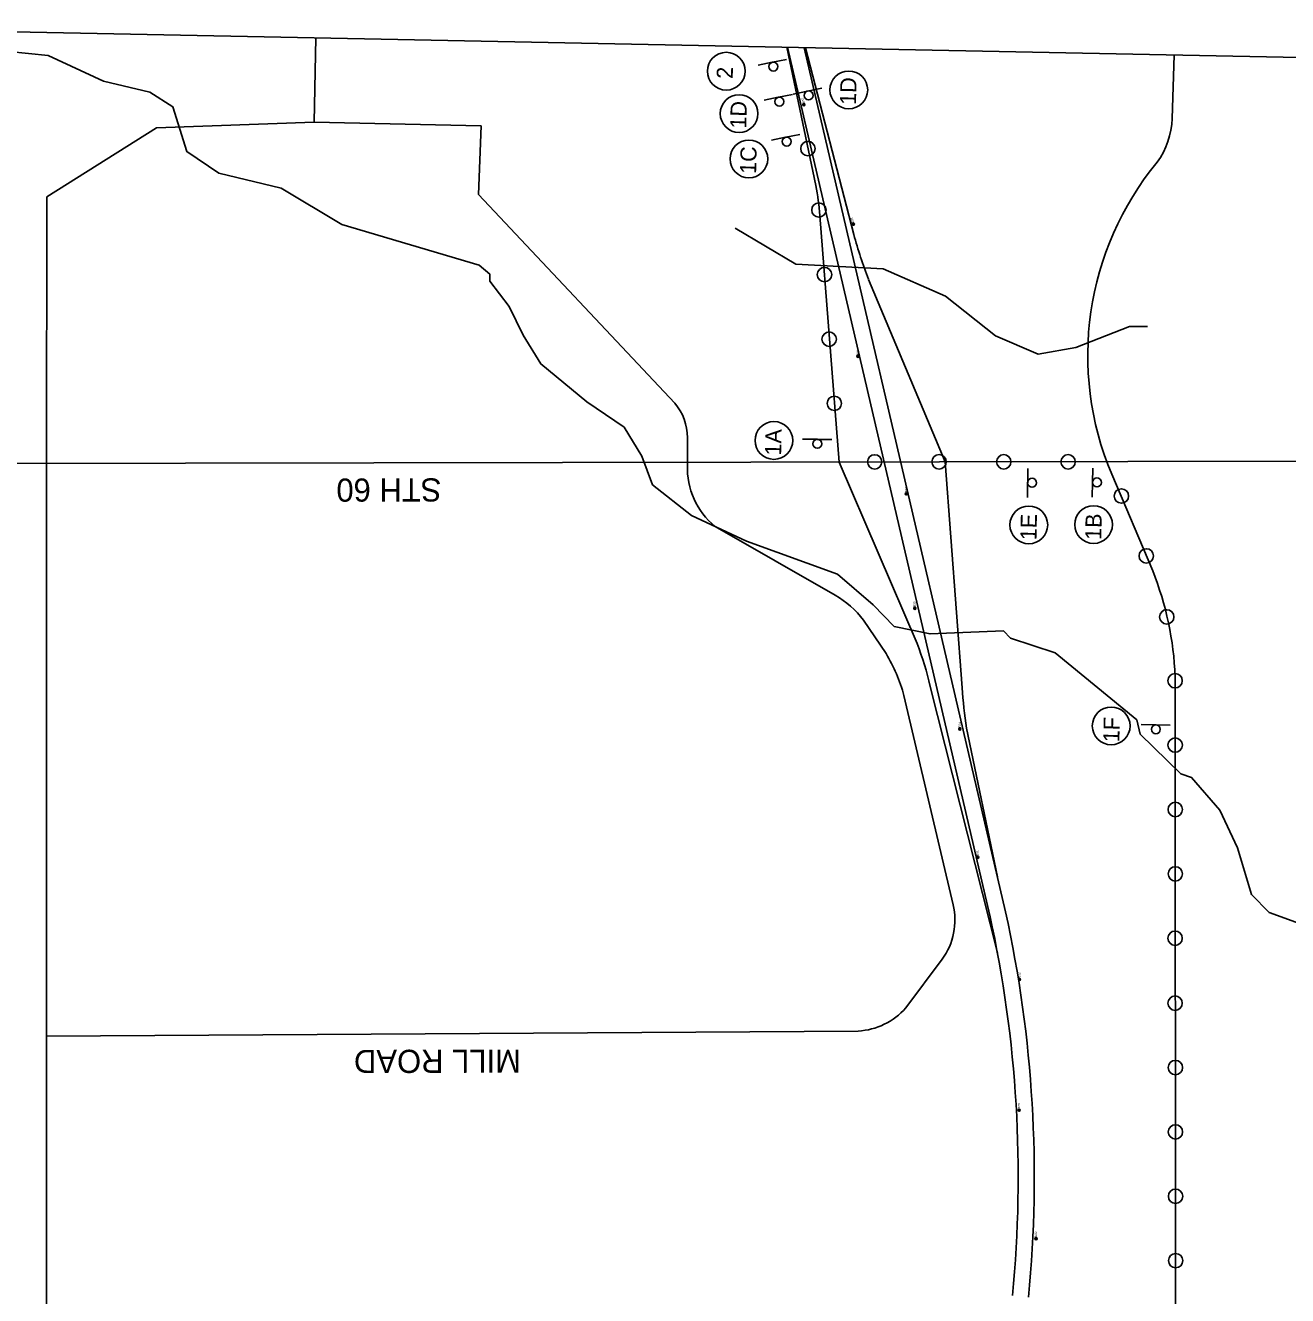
# Model space of a CAD drawing. Extents: x 331323 to 388339, y 121519 to 205315.
# Drawn here: x 357309 to 363194, y 144251 to 150171 of the extents above; entities that cross this region are included whole.
import ezdxf

# ---------------------------------------------------------------- set-up
doc = ezdxf.new("R2010")
doc.units = 0
for name, color, linetype in [('CA-TEXT', 7, 'Continuous'), ('CE-TOPO-CONC-SLAB', 7, 'Continuous'), ('E_SOIL_BORE1 [KAPUR_CADDS_LEVELS]', 7, 'Continuous'), ('E_SOIL_BORE2 [KAPUR_CADDS_LEVELS]', 7, 'Continuous'), ('Level 2', 7, 'Continuous'), ('Level 3', 7, 'Continuous'), ('Level 4', 7, 'Continuous'), ('Level 57', 7, 'Continuous'), ('P_MARK', 7, 'Continuous'), ('PLT_Sheet_Info', 7, 'Continuous'), ('SIGNS-POLES', 7, 'Continuous')]:
    doc.layers.add(name, color=color, linetype=linetype)

msp = doc.modelspace()

# ---------------------------------------------------------------- linework, layer by layer
at = {"layer": 'CA-TEXT'}
for centre in [(360576.8, 149957.2), (361147.9, 149870.1), (360636.3, 149759.4), (360682.2, 149548.3), (360798.8, 148236.2), (361987.2, 147842.8), (362289.2, 147844.4), (362371.3, 146906.1)]:
    msp.add_circle(centre, 88, dxfattribs=at)
at = {"layer": 'CE-TOPO-CONC-SLAB'}
for centre in [(360957.2, 149596.5), (361008.3, 149310.2), (361034.7, 149009.2), (361056.4, 148708.3), (361080.6, 148409.2), (361268.6, 148136.6), (361568.7, 148136.7), (361870.4, 148136.7), (362170.4, 148136.8), (362418.9, 147977.5), (362534.8, 147698.5), (362630.5, 147414.2), (362669.3, 147116.6), (362669.6, 146816.6), (362670, 146516.6), (362670.3, 146216.6), (362669.3, 145916.6), (362669.3, 145614.1), (362670.7, 145314), (362671, 145014.1), (362671.3, 144714.1), (362671.7, 144414.1)]:
    msp.add_circle(centre, 33.5, dxfattribs=at)
at = {"layer": 'Level 2'}
for p, q in [((360993.9, 149424.2), (360859.4, 150068.4)), ((361805.5, 146023.2), (360862.5, 150068.4)), ((361878.5, 146040.2), (360939.9, 150066.8)), ((361171, 149195.5), (360945.9, 150066.7)), ((361102.9, 148135.5), (361012.8, 149285)), ((361597.4, 148136.4), (361239.3, 148987.2)), ((361102.9, 148135.5), (361466.5, 147289.5)), ((361597.4, 148136.4), (361676.1, 147084)), ((361528, 147090.3), (361841.1, 145848)), ((361696.2, 146895.8), (361840.7, 146202.3))]:
    msp.add_line(p, q, dxfattribs=at)
for centre, radius, start, end in [((359828.4, 149195), 1187.8, 4.34586, 11.12726), ((363539.2, 149856.5), 2458.6, 195.59569, 200.70516), ((359972.6, 146718.9), 1599.2, 13.4307, 20.90561), ((364297.5, 147267.9), 2627.8, 184.01299, 188.13954), ((356248.8, 144803.5), 5764, 354.42954, 12.3898), ((356248.8, 144803.5), 5689, 354.42954, 12.3898)]:
    msp.add_arc(centre, radius, start, end, dxfattribs=at)
at = {"layer": 'Level 3'}
for p, q in [((362655.2, 149736.6), (362664.2, 150032.1)), ((363933.7, 148140.4), (355745.4, 148126.3)), ((362374.1, 148078.8), (362564.7, 147628.5)), ((362672.8, 142845.1), (362669.2, 147136.3))]:
    msp.add_line(p, q, dxfattribs=at)
for centre, radius, start, end in [((362295.7, 149745.7), 359.6, 323.74261, 358.54958), ((363679.7, 148631.4), 1417.7, 140.50233, 202.93922), ((361200.1, 147081.5), 1470.2, 2.13732, 21.8455)]:
    msp.add_arc(centre, radius, start, end, dxfattribs=at)
at = {"layer": 'Level 4'}
for p, q in [((358654.7, 149719.2), (358662.6, 150112.7)), ((357920.5, 149692.5), (358654.7, 149719.2)), ((358654.7, 149719.2), (359433.9, 149702.6)), ((359433.9, 149702.6), (359421.5, 149382.3)), ((357408.8, 149372.1), (357920.5, 149692.5)), ((357407, 148129.2), (357408.8, 149372.1)), ((360336.2, 148410.4), (359421.5, 149382.3)), ((360395.8, 148121.9), (360396.2, 148249.2)), ((361085, 147515), (360524.5, 147835.6)), ((361321.4, 147243.2), (361216.1, 147399.5)), ((361634, 146072.7), (361405.1, 147047.4)), ((361413.3, 145592), (361583.8, 145818.9)), ((357407.3, 145459.6), (361191.8, 145484.2))]:
    msp.add_line(p, q, dxfattribs=at)
msp.add_lwpolyline([(357407, 148129.2), (357408.1, 137546.8)], dxfattribs=at)
for centre, radius, start, end in [((360142.1, 148246.4), 254.2, 0.63993, 40.19511), ((360745.7, 148107.1), 350.2, 177.57606, 230.83745), ((360862.6, 147130.3), 444.4, 37.28503, 59.96304), ((360674, 146850.8), 757.1, 15.05941, 31.22122), ((361333.2, 146000.3), 309.4, 324.09067, 13.52297), ((361175.1, 145800.1), 316.3, 273.02875, 318.85042)]:
    msp.add_arc(centre, radius, start, end, dxfattribs=at)
at = {"layer": 'Level 57'}
for points in [[(357231.6, 150048.7), (357414.9, 150030.4), (357672.3, 149911.4), (357888.7, 149859.5), (357996.5, 149791.8), (358061.3, 149582.9), (358210.5, 149481.5), (358501.7, 149412.2), (358783.7, 149243), (359424.1, 149053.9), (359473.8, 149011.8), (359473.5, 148978.4), (359564.1, 148860.9), (359629.6, 148727), (359711.8, 148592.9), (359927, 148416), (360101, 148297.7), (360183.2, 148163.6), (360232, 148029.9), (360414.2, 147886.5), (360671.6, 147767.5), (361095.5, 147613.7), (361261, 147470.5), (361360.1, 147369.6), (361526.6, 147334.8), (361868.7, 147348.4), (361901.7, 147314.7), (362109.6, 147246.2), (362490.3, 146934.4), (362506.4, 146867.6), (362696.5, 146682.5), (362746.4, 146665.4), (362878.4, 146514.2), (362960.2, 146338.5), (363024.9, 146121.2), (363107.5, 146037.1), (363248.9, 145985.8)], [(360618.3, 149226.4), (360900.3, 149057.2), (361308.8, 149036.8), (361599.5, 148909.2), (361831.3, 148723.7), (362030.7, 148638.6), (362206.1, 148670.3), (362457.2, 148768.1), (362540.6, 148767.3)]]:
    msp.add_lwpolyline(points, dxfattribs=at)
at = {"layer": 'P_MARK'}
for p, q in [((360933.5, 149801.2), (360943.5, 149801.2)), ((360938.5, 149806.2), (360938.5, 149796.2)), ((361164.4, 149244.4), (361174.4, 149244.4)), ((361169.4, 149249.4), (361169.4, 149239.4)), ((361185.6, 148628.1), (361195.6, 148628.1)), ((361190.6, 148633.1), (361190.6, 148623.1)), ((361410.8, 147987.9), (361420.8, 147987.9)), ((361415.8, 147992.9), (361415.8, 147982.9)), ((361451, 147454.1), (361461, 147454.1)), ((361456, 147459.1), (361456, 147449.1)), ((361660.8, 146891.4), (361670.8, 146891.4)), ((361665.8, 146896.4), (361665.8, 146886.4)), ((361743.9, 146293.4), (361753.9, 146293.4)), ((361748.9, 146298.4), (361748.9, 146288.4)), ((361938.7, 145724.1), (361948.7, 145724.1)), ((361943.7, 145729.1), (361943.7, 145719.1)), ((361937.3, 145115.6), (361947.3, 145115.6)), ((361942.3, 145120.6), (361942.3, 145110.6)), ((362015.7, 144516.7), (362025.7, 144516.7)), ((362020.7, 144521.7), (362020.7, 144511.7))]:
    msp.add_line(p, q, dxfattribs=at)
for centre in [(360938.5, 149801.2), (361169.4, 149244.4), (361190.6, 148628.1), (361415.8, 147987.9), (361456, 147454.1), (361665.8, 146891.4), (361748.9, 146293.4), (361943.7, 145724.1), (361942.3, 145115.6), (362020.7, 144516.7)]:
    msp.add_circle(centre, 5, dxfattribs=at)
for centre, radius, start, end in [((360938.5, 149801.2), 4.5, 89.98693, 179.98693), ((360938.5, 149801.2), 4, 89.98693, 179.98693), ((360938.5, 149801.2), 3.5, 89.98693, 179.98693), ((360938.5, 149801.2), 3, 89.98693, 179.98693), ((360938.5, 149801.2), 2.5, 89.98693, 179.98693), ((360938.5, 149801.2), 2, 89.98693, 179.98693), ((360938.5, 149801.2), 1.5, 89.98693, 179.98693), ((360938.5, 149801.2), 1, 89.98693, 179.98693), ((360938.5, 149801.2), 0.5, 89.98693, 179.98693), ((360938.5, 149801.2), 4.5, 269.98693, 359.98693), ((360938.5, 149801.2), 4, 269.98693, 359.98693), ((360938.5, 149801.2), 3.5, 269.98693, 359.98693), ((360938.5, 149801.2), 3, 269.98693, 359.98693), ((360938.5, 149801.2), 2.5, 269.98693, 359.98693), ((360938.5, 149801.2), 2, 269.98693, 359.98693), ((360938.5, 149801.2), 1.5, 269.98693, 359.98693), ((360938.5, 149801.2), 1, 269.98693, 359.98693), ((360938.5, 149801.2), 0.5, 269.98693, 359.98693), ((361169.4, 149244.4), 4.5, 89.98693, 179.98693), ((361169.4, 149244.4), 4, 89.98693, 179.98693), ((361169.4, 149244.4), 3.5, 89.98693, 179.98693), ((361169.4, 149244.4), 3, 89.98693, 179.98693), ((361169.4, 149244.4), 2.5, 89.98693, 179.98693), ((361169.4, 149244.4), 2, 89.98693, 179.98693), ((361169.4, 149244.4), 1.5, 89.98693, 179.98693), ((361169.4, 149244.4), 1, 89.98693, 179.98693), ((361169.4, 149244.4), 0.5, 89.98693, 179.98693), ((361169.4, 149244.4), 4.5, 269.98693, 359.98693), ((361169.4, 149244.4), 4, 269.98693, 359.98693), ((361169.4, 149244.4), 3.5, 269.98693, 359.98693), ((361169.4, 149244.4), 3, 269.98693, 359.98693), ((361169.4, 149244.4), 2.5, 269.98693, 359.98693), ((361169.4, 149244.4), 2, 269.98693, 359.98693), ((361169.4, 149244.4), 1.5, 269.98693, 359.98693), ((361169.4, 149244.4), 1, 269.98693, 359.98693), ((361169.4, 149244.4), 0.5, 269.98693, 359.98693), ((361190.6, 148628.1), 4.5, 89.98693, 179.98693), ((361190.6, 148628.1), 4, 89.98693, 179.98693), ((361190.6, 148628.1), 3.5, 89.98693, 179.98693), ((361190.6, 148628.1), 3, 89.98693, 179.98693), ((361190.6, 148628.1), 2.5, 89.98693, 179.98693), ((361190.6, 148628.1), 2, 89.98693, 179.98693), ((361190.6, 148628.1), 1.5, 89.98693, 179.98693), ((361190.6, 148628.1), 1, 89.98693, 179.98693), ((361190.6, 148628.1), 0.5, 89.98693, 179.98693), ((361190.6, 148628.1), 4.5, 269.98693, 359.98693), ((361190.6, 148628.1), 4, 269.98693, 359.98693), ((361190.6, 148628.1), 3.5, 269.98693, 359.98693), ((361190.6, 148628.1), 3, 269.98693, 359.98693), ((361190.6, 148628.1), 2.5, 269.98693, 359.98693), ((361190.6, 148628.1), 2, 269.98693, 359.98693), ((361190.6, 148628.1), 1.5, 269.98693, 359.98693), ((361190.6, 148628.1), 1, 269.98693, 359.98693), ((361190.6, 148628.1), 0.5, 269.98693, 359.98693), ((361415.8, 147987.9), 4.5, 89.98693, 179.98693), ((361415.8, 147987.9), 4, 89.98693, 179.98693), ((361415.8, 147987.9), 3.5, 89.98693, 179.98693), ((361415.8, 147987.9), 3, 89.98693, 179.98693), ((361415.8, 147987.9), 2.5, 89.98693, 179.98693), ((361415.8, 147987.9), 2, 89.98693, 179.98693), ((361415.8, 147987.9), 1.5, 89.98693, 179.98693), ((361415.8, 147987.9), 1, 89.98693, 179.98693), ((361415.8, 147987.9), 0.5, 89.98693, 179.98693), ((361415.8, 147987.9), 4.5, 269.98693, 359.98693), ((361415.8, 147987.9), 4, 269.98693, 359.98693), ((361415.8, 147987.9), 3.5, 269.98693, 359.98693), ((361415.8, 147987.9), 3, 269.98693, 359.98693), ((361415.8, 147987.9), 2.5, 269.98693, 359.98693), ((361415.8, 147987.9), 2, 269.98693, 359.98693), ((361415.8, 147987.9), 1.5, 269.98693, 359.98693), ((361415.8, 147987.9), 1, 269.98693, 359.98693), ((361415.8, 147987.9), 0.5, 269.98693, 359.98693), ((361456, 147454.1), 4.5, 89.98693, 179.98693), ((361456, 147454.1), 4, 89.98693, 179.98693), ((361456, 147454.1), 3.5, 89.98693, 179.98693), ((361456, 147454.1), 3, 89.98693, 179.98693), ((361456, 147454.1), 2.5, 89.98693, 179.98693), ((361456, 147454.1), 2, 89.98693, 179.98693), ((361456, 147454.1), 1.5, 89.98693, 179.98693), ((361456, 147454.1), 1, 89.98693, 179.98693), ((361456, 147454.1), 0.5, 89.98693, 179.98693), ((361456, 147454.1), 4.5, 269.98693, 359.98693), ((361456, 147454.1), 4, 269.98693, 359.98693), ((361456, 147454.1), 3.5, 269.98693, 359.98693), ((361456, 147454.1), 3, 269.98693, 359.98693), ((361456, 147454.1), 2.5, 269.98693, 359.98693), ((361456, 147454.1), 2, 269.98693, 359.98693), ((361456, 147454.1), 1.5, 269.98693, 359.98693), ((361456, 147454.1), 1, 269.98693, 359.98693), ((361456, 147454.1), 0.5, 269.98693, 359.98693), ((361665.8, 146891.4), 4.5, 89.98693, 179.98693), ((361665.8, 146891.4), 4, 89.98693, 179.98693), ((361665.8, 146891.4), 3.5, 89.98693, 179.98693), ((361665.8, 146891.4), 3, 89.98693, 179.98693), ((361665.8, 146891.4), 2.5, 89.98693, 179.98693), ((361665.8, 146891.4), 2, 89.98693, 179.98693), ((361665.8, 146891.4), 1.5, 89.98693, 179.98693), ((361665.8, 146891.4), 1, 89.98693, 179.98693), ((361665.8, 146891.4), 0.5, 89.98693, 179.98693), ((361665.8, 146891.4), 4.5, 269.98693, 359.98693), ((361665.8, 146891.4), 4, 269.98693, 359.98693), ((361665.8, 146891.4), 3.5, 269.98693, 359.98693), ((361665.8, 146891.4), 3, 269.98693, 359.98693), ((361665.8, 146891.4), 2.5, 269.98693, 359.98693), ((361665.8, 146891.4), 2, 269.98693, 359.98693), ((361665.8, 146891.4), 1.5, 269.98693, 359.98693), ((361665.8, 146891.4), 1, 269.98693, 359.98693), ((361665.8, 146891.4), 0.5, 269.98693, 359.98693), ((361748.9, 146293.4), 4.5, 89.98693, 179.98693), ((361748.9, 146293.4), 4, 89.98693, 179.98693), ((361748.9, 146293.4), 3.5, 89.98693, 179.98693), ((361748.9, 146293.4), 3, 89.98693, 179.98693), ((361748.9, 146293.4), 2.5, 89.98693, 179.98693), ((361748.9, 146293.4), 2, 89.98693, 179.98693), ((361748.9, 146293.4), 1.5, 89.98693, 179.98693), ((361748.9, 146293.4), 1, 89.98693, 179.98693), ((361748.9, 146293.4), 0.5, 89.98693, 179.98693), ((361748.9, 146293.4), 4.5, 269.98693, 359.98693), ((361748.9, 146293.4), 4, 269.98693, 359.98693), ((361748.9, 146293.4), 3.5, 269.98693, 359.98693), ((361748.9, 146293.4), 3, 269.98693, 359.98693), ((361748.9, 146293.4), 2.5, 269.98693, 359.98693), ((361748.9, 146293.4), 2, 269.98693, 359.98693), ((361748.9, 146293.4), 1.5, 269.98693, 359.98693), ((361748.9, 146293.4), 1, 269.98693, 359.98693), ((361748.9, 146293.4), 0.5, 269.98693, 359.98693), ((361943.7, 145724.1), 4.5, 89.98693, 179.98693), ((361943.7, 145724.1), 4, 89.98693, 179.98693), ((361943.7, 145724.1), 3.5, 89.98693, 179.98693), ((361943.7, 145724.1), 3, 89.98693, 179.98693), ((361943.7, 145724.1), 2.5, 89.98693, 179.98693), ((361943.7, 145724.1), 2, 89.98693, 179.98693), ((361943.7, 145724.1), 1.5, 89.98693, 179.98693), ((361943.7, 145724.1), 1, 89.98693, 179.98693), ((361943.7, 145724.1), 0.5, 89.98693, 179.98693), ((361943.7, 145724.1), 4.5, 269.98693, 359.98693), ((361943.7, 145724.1), 4, 269.98693, 359.98693), ((361943.7, 145724.1), 3.5, 269.98693, 359.98693), ((361943.7, 145724.1), 3, 269.98693, 359.98693), ((361943.7, 145724.1), 2.5, 269.98693, 359.98693), ((361943.7, 145724.1), 2, 269.98693, 359.98693), ((361943.7, 145724.1), 1.5, 269.98693, 359.98693), ((361943.7, 145724.1), 1, 269.98693, 359.98693), ((361943.7, 145724.1), 0.5, 269.98693, 359.98693), ((361942.3, 145115.6), 4.5, 89.98693, 179.98693), ((361942.3, 145115.6), 4, 89.98693, 179.98693), ((361942.3, 145115.6), 3.5, 89.98693, 179.98693), ((361942.3, 145115.6), 3, 89.98693, 179.98693), ((361942.3, 145115.6), 2.5, 89.98693, 179.98693), ((361942.3, 145115.6), 2, 89.98693, 179.98693), ((361942.3, 145115.6), 1.5, 89.98693, 179.98693), ((361942.3, 145115.6), 1, 89.98693, 179.98693), ((361942.3, 145115.6), 0.5, 89.98693, 179.98693), ((361942.3, 145115.6), 4.5, 269.98693, 359.98693), ((361942.3, 145115.6), 4, 269.98693, 359.98693), ((361942.3, 145115.6), 3.5, 269.98693, 359.98693), ((361942.3, 145115.6), 3, 269.98693, 359.98693), ((361942.3, 145115.6), 2.5, 269.98693, 359.98693), ((361942.3, 145115.6), 2, 269.98693, 359.98693), ((361942.3, 145115.6), 1.5, 269.98693, 359.98693), ((361942.3, 145115.6), 1, 269.98693, 359.98693), ((361942.3, 145115.6), 0.5, 269.98693, 359.98693), ((362020.7, 144516.7), 4.5, 89.98693, 179.98693), ((362020.7, 144516.7), 4, 89.98693, 179.98693), ((362020.7, 144516.7), 3.5, 89.98693, 179.98693), ((362020.7, 144516.7), 3, 89.98693, 179.98693), ((362020.7, 144516.7), 2.5, 89.98693, 179.98693), ((362020.7, 144516.7), 2, 89.98693, 179.98693), ((362020.7, 144516.7), 1.5, 89.98693, 179.98693), ((362020.7, 144516.7), 1, 89.98693, 179.98693), ((362020.7, 144516.7), 0.5, 89.98693, 179.98693), ((362020.7, 144516.7), 4.5, 269.98693, 359.98693), ((362020.7, 144516.7), 4, 269.98693, 359.98693), ((362020.7, 144516.7), 3.5, 269.98693, 359.98693), ((362020.7, 144516.7), 3, 269.98693, 359.98693), ((362020.7, 144516.7), 2.5, 269.98693, 359.98693), ((362020.7, 144516.7), 2, 269.98693, 359.98693), ((362020.7, 144516.7), 1.5, 269.98693, 359.98693), ((362020.7, 144516.7), 1, 269.98693, 359.98693), ((362020.7, 144516.7), 0.5, 269.98693, 359.98693)]:
    msp.add_arc(centre, radius, start, end, dxfattribs=at)
at = {"layer": 'PLT_Sheet_Info'}
msp.add_line((367784.1, 149929), (355786.5, 150170.6), dxfattribs=at)
at = {"layer": 'SIGNS-POLES'}
for p, q in [((360724.9, 149985.5), (360791, 149999.4)), ((360791.6, 149999), (360857.7, 150012.4)), ((360753.1, 149822), (360819.1, 149835.9)), ((360819.7, 149835.5), (360885.9, 149849)), ((360888.9, 149850.8), (360955, 149864.7)), ((360955.5, 149864.3), (361021.7, 149877.7)), ((360787.1, 149635.9), (360853.2, 149649.8)), ((360853.8, 149649.4), (360919.9, 149662.8)), ((360932.7, 148242.8), (361000.2, 148242)), ((361000.7, 148241.4), (361068.2, 148240.1)), ((361981.9, 148038.7), (361983.2, 148106.2)), ((362283.9, 148040.3), (362285.3, 148107.8)), ((361980.5, 147970.7), (361981.4, 148038.2)), ((362282.6, 147972.3), (362283.4, 148039.8)), ((362511.1, 146912.6), (362578.6, 146911.7)), ((362579.1, 146911.2), (362646.6, 146909.8))]:
    msp.add_line(p, q, dxfattribs=at)
for centre in [(360796.5, 149978.9), (360824.6, 149815.4), (360960.4, 149844.1), (360858.7, 149629.2), (361001.1, 148220.7), (362002.6, 148039.1), (362304.7, 148040.7), (362579.5, 146890.4)]:
    msp.add_circle(centre, 20.9, dxfattribs=at)

# ---------------------------------------------------------------- texts
at = {"layer": 'CA-TEXT'}
for s, height, rotation, p in [('2', 75, 88.84682, (360606.7, 149920.9)), ('1D', 75, 88.84682, (361181.4, 149799.8)), ('1D', 75, 88.84682, (360669.7, 149689.1)), ('1C', 75, 88.84682, (360715.7, 149478)), ('1A', 75, 88.84682, (360832.3, 148165.9)), ('STH 60', 108, 180.11947, (359248.4, 148060)), ('1E', 75, 88.84682, (362022.8, 147771)), ('1B', 75, 88.84682, (362324.8, 147772.6)), ('1F', 75, 88.84682, (362409.3, 146829.4)), ('MILL ROAD', 108, 180.11947, (359619.2, 145397.9))]:
    msp.add_text(s, height=height, rotation=rotation, dxfattribs=at).set_placement(p)
at = {"layer": 'E_SOIL_BORE1 [KAPUR_CADDS_LEVELS]'}
for s, rotation, p in [('B37', 105.74655, (360942.9, 149810.5)), ('B33', 89.98693, (361459.1, 147461.4)), ('B34', 89.98693, (361670.1, 146898.6)), ('B30', 89.98693, (362025.2, 144524.8))]:
    msp.add_text(s, height=10, rotation=rotation, dxfattribs=at).set_placement(p)
at = {"layer": 'E_SOIL_BORE2 [KAPUR_CADDS_LEVELS]'}
for s, rotation, p in [('B38', 105.74655, (361172.2, 149251.8)), ('B35', 89.98693, (361194.1, 148637)), ('B36', 89.98693, (361420.2, 147995.1)), ('B31', 89.98693, (361752, 146301.8)), ('B32', 89.98693, (361947.6, 145732.9)), ('B29', 89.98693, (361946.8, 145122.2))]:
    msp.add_text(s, height=10, rotation=rotation, dxfattribs=at).set_placement(p)

doc.saveas('drawing.dxf')
